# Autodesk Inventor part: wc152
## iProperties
Shininess: 64.0
Length Units: 11272
Angle Units: 11279
Time Units: 11290
Mass Units: 11286
Length Display Precision: 3
Angle Display Precision: 2
Compacted: True
Part Number: wc152
Document SubType Name: Modeling
Created: 2004-08
Designer: John Blackburn
Manufacturer: Standard
Standards Organization: Custom
Density: 0.0
Volumn: 0.0
Area: 0.0
PropertySet Name: Model Information
Control State: 0
Master: False
Checked Out: False
Author: John Blackburn
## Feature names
1. Base1
